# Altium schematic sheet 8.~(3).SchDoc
size 398 x 287 mm
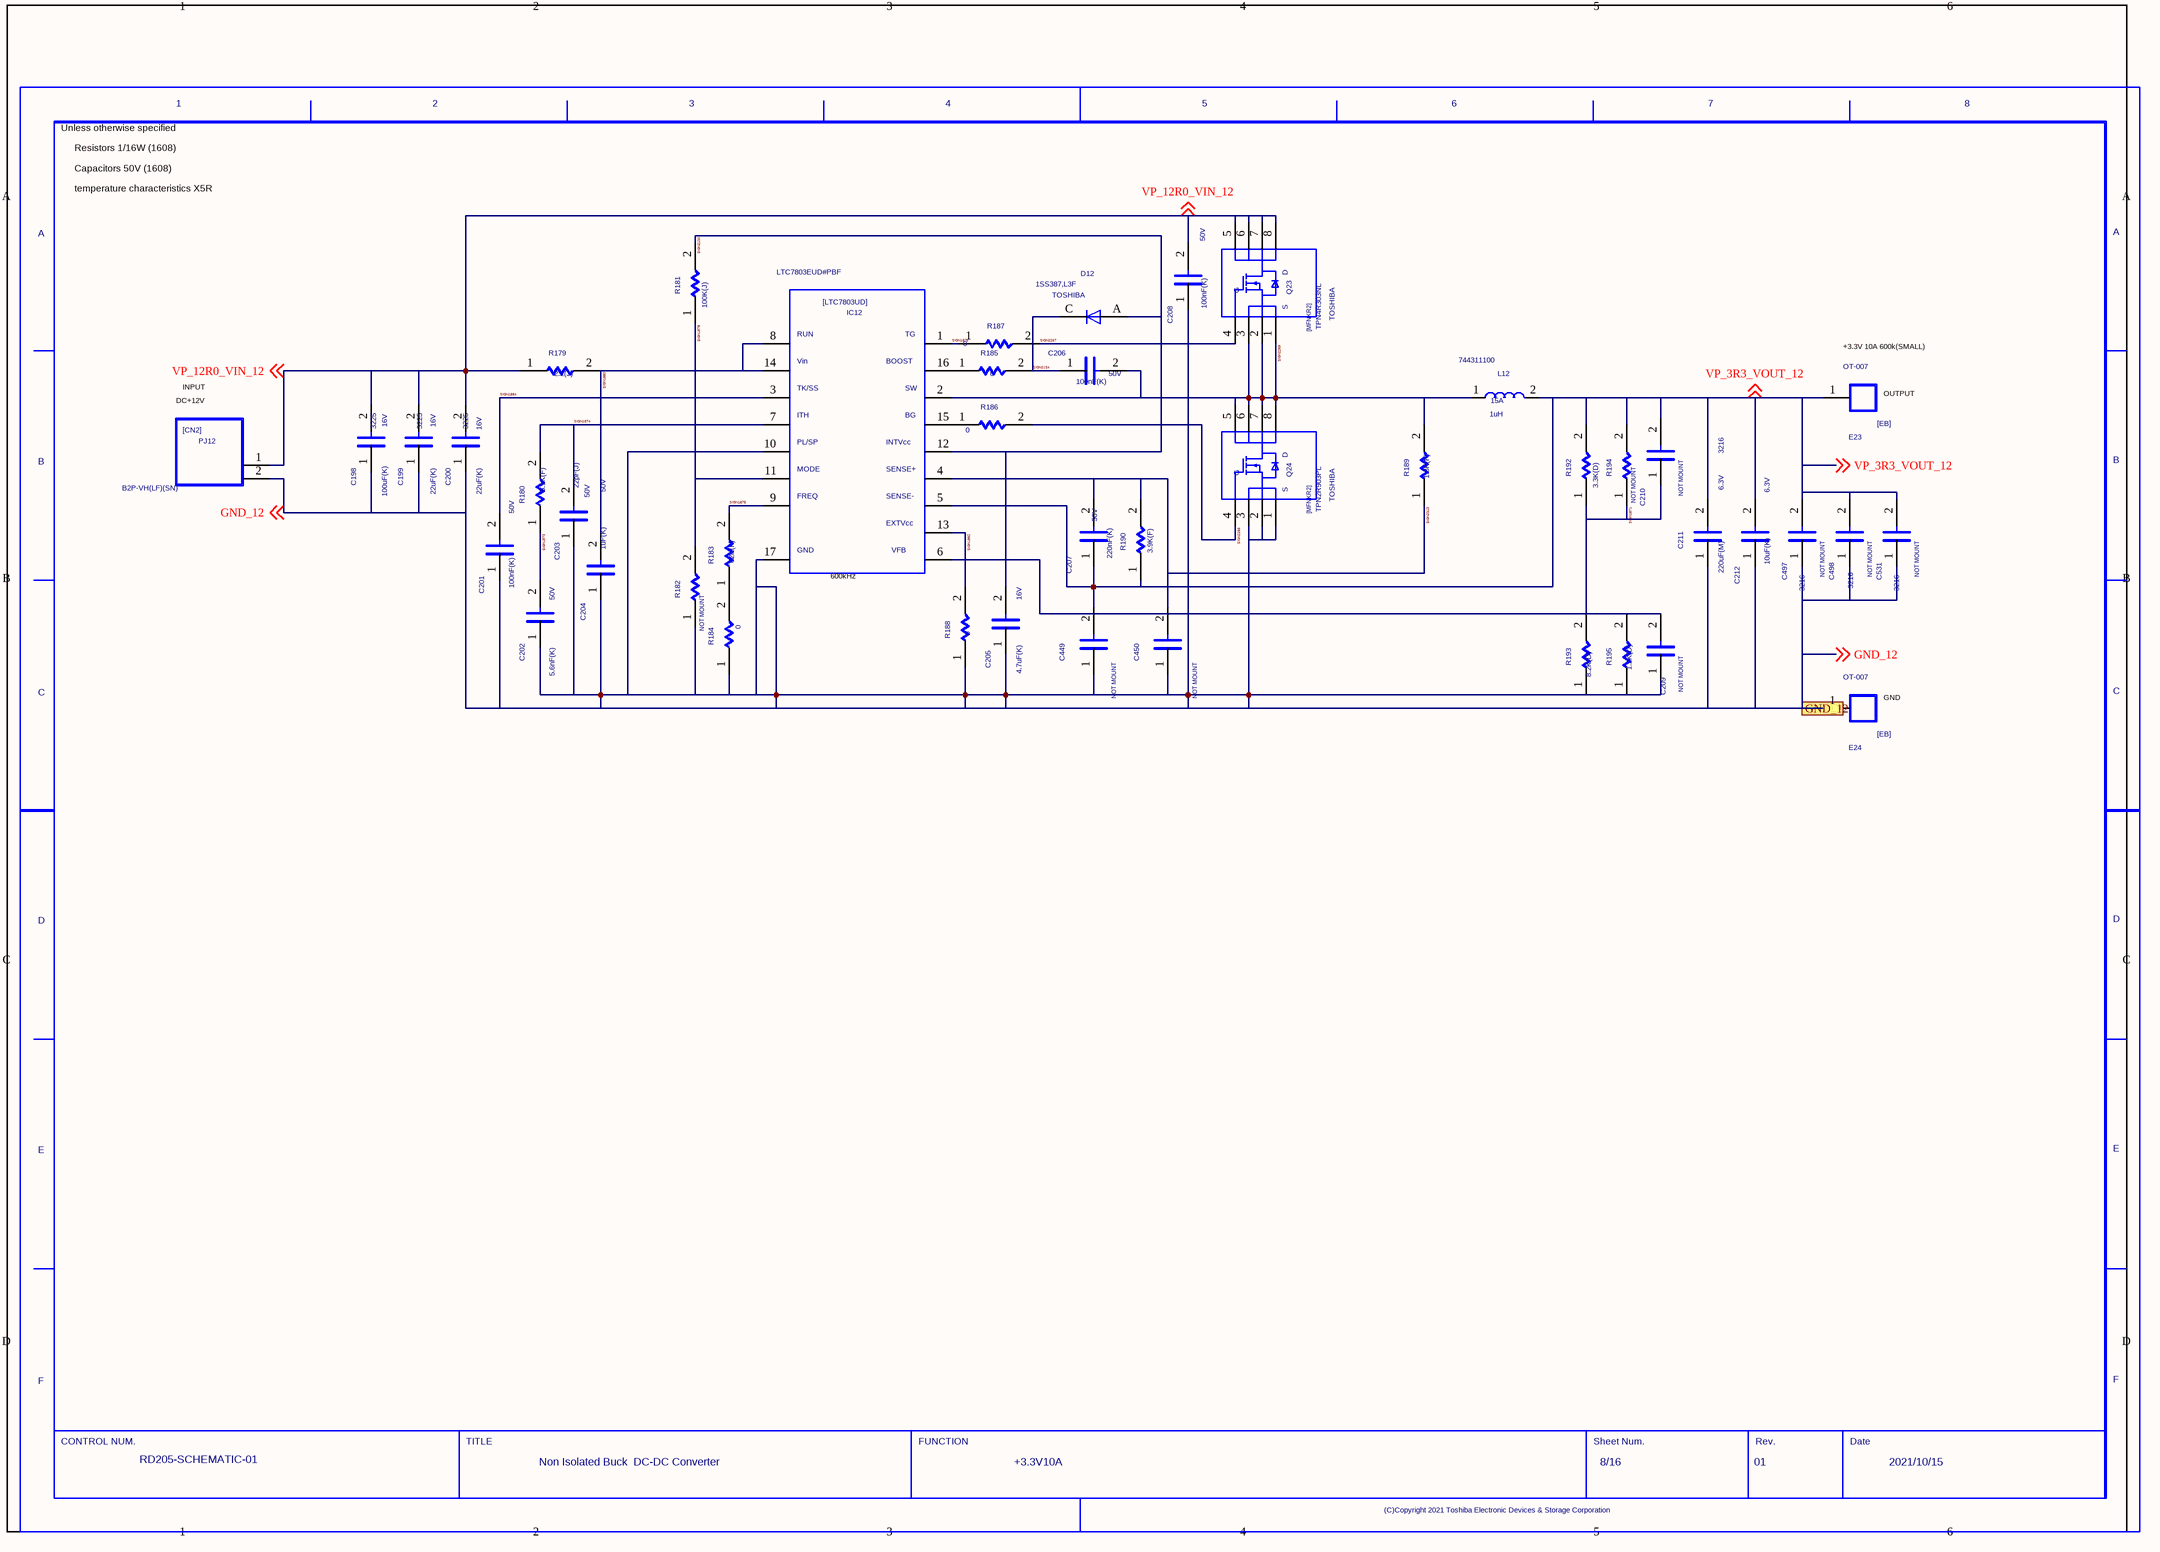
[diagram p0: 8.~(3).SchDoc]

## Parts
C198  SIZECODESMD: 3225  VAL2: 16V  VAL1: 100uF(K)  (hidden comment: C)
C199  SIZECODESMD: 3225  VAL2: 16V  VAL1: 22uF(K)  (hidden comment: C)
C200  SIZECODESMD: 3225  VAL2: 16V  VAL1: 22uF(K)  (hidden comment: C)
C201  VAL2: 50V  VAL1: 100nF(K)  (hidden comment: C)
C202  VAL2: 50V  VAL1: 5.6nF(K)  (hidden comment: C)
C203  VAL2: 50V  VAL1: 22pF(J)  (hidden comment: C)
C204  VAL2: 50V  VAL1: 1uF(K)  (hidden comment: C)
C205  VAL2: 16V  VAL1: 4.7uF(K)  (hidden comment: C)
C206  VAL2: 50V  VAL1: 100nF(K)  (hidden comment: C)
C207  VAL2: 50V  VAL1: 220nF(K)  (hidden comment: C)
C208  VAL2: 50V  VAL1: 100nF(K)  (hidden comment: C)
C209  NOTMOUNT: NOT MOUNT  (hidden comment: C)
C210  NOTMOUNT: NOT MOUNT  (hidden comment: C)
C211  SIZECODESMD: 3216  VAL2: 6.3V  VAL1: 220uF(M)  (hidden comment: C)
C212  VAL2: 6.3V  VAL1: 10uF(K)  (hidden comment: C)
C449  NOTMOUNT: NOT MOUNT  (hidden comment: C)
C450  NOTMOUNT: NOT MOUNT  (hidden comment: C)
C497  NOTMOUNT: NOT MOUNT  SIZECODESMD: 3216  (hidden comment: C)
C498  NOTMOUNT: NOT MOUNT  SIZECODESMD: 3216  (hidden comment: C)
C531  NOTMOUNT: NOT MOUNT  SIZECODESMD: 3216  (hidden comment: C)
D12  USERCOMPTEXT3: TOSHIBA  VAL3: 1SS387,L3F  (hidden comment: D)
E23  VAL3: OT-007  (hidden comment: EB)
E24  VAL3: OT-007  (hidden comment: EB)
IC12  VAL3: LTC7803EUD#PBF  (hidden comment: LTC7803UD)
L12  VAL3: 744311100  VAL2: 15A  VAL1: 1uH  (hidden comment: L)
PJ12  VAL3: B2P-VH(LF)(SN)  (hidden comment: CN2)
Q23  USERCOMPTEXT3: TOSHIBA  VAL3: TPN4R303NL  (hidden comment: MFNKR2)
Q24  USERCOMPTEXT3: TOSHIBA  VAL3: TPN2R903PL  (hidden comment: MFNKR2)
R179  VAL1: 2.2(J)  (hidden comment: R)
R180  VAL1: 5.1K(F)  (hidden comment: R)
R181  VAL1: 100K(J)  (hidden comment: R)
R182  NOTMOUNT: NOT MOUNT  (hidden comment: R)
R183  VAL1: 62K(F)  (hidden comment: R)
R184  VAL1: 0  (hidden comment: R)
R185  VAL1: 0  (hidden comment: R)
R186  VAL1: 0  (hidden comment: R)
R187  VAL1: 0  (hidden comment: R)
R188  VAL1: 0  (hidden comment: R)
R189  VAL1: 1.3K(F)  (hidden comment: R)
R190  VAL1: 3.9K(F)  (hidden comment: R)
R192  VAL1: 3.3K(D)  (hidden comment: R)
R193  VAL1: 8.2K(D)  (hidden comment: R)
R194  NOTMOUNT: NOT MOUNT  (hidden comment: R)
R195  VAL1: 1.2K(D)  (hidden comment: R)
U?  DATE: 2021/10/15  SHEETNUMBER: 8/16  TITLE: Non Isolated Buck / DC-DC Converter  REVISION: 01  DRAWINGNUMBER: RD205-SCHEMATIC-01  FUNCTION: +3.3V10A  (hidden comment: WAKU_DEF100)

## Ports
GND_12

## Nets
GND_12: C198.1 C199.1 C200.1 C201.1 C202.1 C203.1 C204.1 C205.1 C208.1 C209.1 C211.1 C212.1 C449.1 C450.1 C497.1 C498.1 C531.1 E24.1 IC12.10 IC12.17 PJ12.2 Q24.1 Q24.2 Q24.3 R182.1 R184.1 R188.1 R193.1 R195.1 ; off-sheet GND_12, port GND_12
SIGN1871: C209.2 C210.1 IC12.6 R192.1 R193.2 R194.1 R195.2
SIGN1873: C202.2 R180.1
SIGN1874: C203.2 IC12.7 R180.2
SIGN1875: IC12.9 R183.2
SIGN1876: IC12.1 R187.1
SIGN1878: IC12.11 R181.1 R182.2
SIGN1880: C204.2 IC12.8 IC12.14 R179.2
SIGN1882: IC12.13 R188.2
SIGN1884: C201.2 IC12.3
SIGN2133: C205.2 D12.A IC12.12 R181.2
SIGN2134: C206.1 D12.C R185.2
SIGN2267: Q23.4 R187.2
SIGN2268: Q24.4 R186.2
SIGN2269: C206.2 IC12.2 L12.1 Q23.1 Q23.2 Q23.3 Q24.5 Q24.6 Q24.7 Q24.8 R189.2
SIGN2313: C207.2 C450.2 IC12.4 R189.1 R190.2
VP_3R3_VOUT_12: C207.1 C210.2 C211.2 C212.2 C449.2 C497.2 C498.2 C531.2 E23.1 IC12.5 L12.2 R190.1 R192.2 R194.2 ; off-sheet VP_3R3_VOUT_12
VP_12R0_VIN_12: C198.2 C199.2 C200.2 C208.2 PJ12.1 Q23.5 Q23.6 Q23.7 Q23.8 R179.1 ; off-sheet VP_12R0_VIN_12
NetIC12_15: IC12.15 R186.1
NetIC12_16: IC12.16 R185.1
NetR183_1: R183.1 R184.2

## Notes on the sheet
- Unless otherwise specified
- Capacitors 50V (1608)
- Resistors 1/16W (1608)
- temperature characteristics X5R
- DC+12V
- INPUT
- (near E23) +3.3V 10A 600k(SMALL)
- (near E23) OUTPUT
- (near IC12) 600kHz
- (near E24) GND

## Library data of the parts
C198 = C: SQ_PART_MODEL: CON_100n; FNPARTSNAMEG: CHIP CERAMIC CAPACITOR (3225); USEINPARTSLIST: YES; OriginalSymbolOrigin: (2540,7620); MFSOLDERINGPROP: .; TEMPCHARACTERI2: B; MFFORMINGDIVP: KC; OUMECLASSIFICATION: セラミックコンデンサ; MFMOUNTSYMBOLP: 90; CDMASTERCADCELG: DC903A; PCODE: P03276001115; FNCLASSCODEG: P03-03; MAXGCOUNT: 1; RATEDVOLTAGE: 250; COMPONENTNAME: G36030160049; OUMEMAKER: KYC 京セラ; MFPACKAGEMETHOP: S; NOMINALCAPACITA: 100n; OUMEMAKERKATAMEI: CF32W5R104K250AT; CAPACITANCETOLE: K
C199 C200 = C: SQ_PART_MODEL: CON_22u; FNPARTSNAMEG: CHIP CERAMIC CAPACITOR (3225); USEINPARTSLIST: YES; OriginalSymbolOrigin: (2540,7620); MFSOLDERINGPROP: .; TEMPCHARACTERI2: B; MFFORMINGDIVP: KC; OUMECLASSIFICATION: セラミックコンデンサ; MFMOUNTSYMBOLP: 80; CDMASTERCADCELG: DC903A; PCODE: P03043035626; FNCLASSCODEG: P03-03; MAXGCOUNT: 1; RATEDVOLTAGE: 6.3; COMPONENTNAME: G36030119054; OUMEMAKER: TYD 太陽誘電; MFPACKAGEMETHOP: S; NOMINALCAPACITA: 22u; OUMEMAKERKATAMEI: JMK325BJ226KM-T; CAPACITANCETOLE: K
C201 C206 C208 = C: SQ_PART_MODEL: CON_100n; FNPARTSNAMEG: CHIP CERAMIC CAPACITOR (1608); USEINPARTSLIST: YES; OriginalSymbolOrigin: (2540,7620); MFSOLDERINGPROP: .; TEMPCHARACTERI2: B; MFFORMINGDIVP: KC; OUMECLASSIFICATION: セラミックコンデンサ; SIZECODESMD: 1608; MFMOUNTSYMBOLP: 80; CDMASTERCADCELG: C8100E; PCODE: P03B000000E4; FNCLASSCODEG: P03-03; MAXGCOUNT: 1; RATEDVOLTAGE: 16; COMPONENTNAME: GDM030000598; OUMEMAKER: MRT 村田製作所; MFPACKAGEMETHOP: S; NOMINALCAPACITA: 100n; OUMEMAKERKATAMEI: GRM188B11C104KA01C; CAPACITANCETOLE: K
C202 = C: SQ_PART_MODEL: CON_5.6n; FNPARTSNAMEG: CHIP CERAMIC CAPACITOR (1608); USEINPARTSLIST: YES; OriginalSymbolOrigin: (2540,7620); TOLERANCE: K; ASIMVALUE: 5.6N; MFSOLDERINGPROP: .; TEMPCHARACTERI2: B; MFFORMINGDIVP: KC; OUMECLASSIFICATION: セラミックコンデンサ; SIZECODESMD: 1608; MFMOUNTSYMBOLP: 80; CDMASTERCADCELG: C8100E; PCODE: P03039100222; FNCLASSCODEG: P03-03; MAXGCOUNT: 1; RATEDVOLTAGE: 50; COMPONENTNAME: G36030011068; OUMEMAKER: MRT 村田製作所; MFPACKAGEMETHOP: S; OUMEMAKERKATAMEI: GRM39B562K50PT
C203 = C: SQ_PART_MODEL: CON_22p; FNPARTSNAMEG: CHIP CERAMIC CAPACITOR (1608); USEINPARTSLIST: YES; OriginalSymbolOrigin: (2540,7620); TOLERANCE: J; ASIMVALUE: 22P; CDMASTERCADCELG: C8100E; MFSOLDERINGPROP: .; TEMPCHARACTERI2: CH; MFFORMINGDIVP: KC; OUMECLASSIFICATION: セラミックコンデンサ; SIZECODESMD: 1608; MFMOUNTSYMBOLP: 80; PCODE: P03039A02625; FNCLASSCODEG: P03-03; MAXGCOUNT: 1; RATEDVOLTAGE: 50; COMPONENTNAME: G36030011129; OUMEMAKER: TYD 太陽誘電; MFPACKAGEMETHOP: S; OUMEMAKERKATAMEI: UMK107CH220JZ-T
C204 = C: SQ_PART_MODEL: CON_1u; FNPARTSNAMEG: CHIP CERAMIC CAPACITOR (1608); USEINPARTSLIST: YES; OriginalSymbolOrigin: (2540,7620); MFSOLDERINGPROP: .; TEMPCHARACTERI2: B; MFFORMINGDIVP: KC; OUMECLASSIFICATION: セラミックコンデンサ; SIZECODESMD: 1608; MFMOUNTSYMBOLP: 80; CDMASTERCADCELG: C8100E; PCODE: P03039ACE122; FNCLASSCODEG: P03-03; MAXGCOUNT: 1; RATEDVOLTAGE: 6.3; COMPONENTNAME: G36030104159; OUMEMAKER: KYC 京セラ; MFPACKAGEMETHOP: S; NOMINALCAPACITA: 1u; OUMEMAKERKATAMEI: CM105B105K06ATN; CAPACITANCETOLE: K
C205 = C: SQ_PART_MODEL: CON_4.7u; FNPARTSNAMEG: CHIP CERAMIC CAPACITOR (1608); USEINPARTSLIST: YES; OriginalSymbolOrigin: (2540,7620); MFSOLDERINGPROP: .; TEMPCHARACTERI2: B; MFFORMINGDIVP: KC; OUMECLASSIFICATION: セラミックコンデンサ; SIZECODESMD: 1608; MFMOUNTSYMBOLP: 80; CDMASTERCADCELG: C8100E; PCODE: P03B000000MS; FNCLASSCODEG: P03-03; MAXGCOUNT: 1; RATEDVOLTAGE: 4; COMPONENTNAME: GDM030000053; OUMEMAKER: KYC 京セラ; MFPACKAGEMETHOP: S; NOMINALCAPACITA: 4.7u; OUMEMAKERKATAMEI: CM105B475M04AT; CAPACITANCETOLE: M
C207 = C: SQ_PART_MODEL: CON_220n; FNPARTSNAMEG: CHIP CERAMIC CAPACITOR (1608); PARTCOMMENT: 代表セル<KC0008> がフットプリントに登録されていません。; USEINPARTSLIST: YES; OriginalSymbolOrigin: (2540,7620); MFSOLDERINGPROP: .; TEMPCHARACTERI2: B; MFFORMINGDIVP: KC; OUMECLASSIFICATION: セラミックコンデンサ; SIZECODESMD: 1608; MFMOUNTSYMBOLP: 80; CDMASTERCADCELG: KC0008; PCODE: P03B000001L3; FNCLASSCODEG: P03-03; MAXGCOUNT: 1; RATEDVOLTAGE: 16; COMPONENTNAME: GDM030001129; OUMEMAKER: MRT 村田製作所; MFPACKAGEMETHOP: S; NOMINALCAPACITA: 220n; OUMEMAKERKATAMEI: GRM188B11C224KA01D; CAPACITANCETOLE: K
C209 C210 = C: SQ_PART_MODEL: CON_100p; FNPARTSNAMEG: CHIP CERAMIC CAPACITOR (1608); USEINPARTSLIST: YES; OriginalSymbolOrigin: (2540,7620); TOLERANCE: J; ASIMVALUE: 100P; MFSOLDERINGPROP: .; TEMPCHARACTERI2: CH; MFFORMINGDIVP: KC; OUMECLASSIFICATION: セラミックコンデンサ; SIZECODESMD: 1608; MFMOUNTSYMBOLP: 80; CDMASTERCADCELG: C8100E; PCODE: P03039177125; FNCLASSCODEG: P03-03; MAXGCOUNT: 1; RATEDVOLTAGE: 50; COMPONENTNAME: G36030011365; OUMEMAKER: KYC 京セラ; MFPACKAGEMETHOP: S; OUMEMAKERKATAMEI: CM105CH101J50AT; VAL2: 50V; VAL1: 100pF(J)
C211 = C: SQ_PART_MODEL: CON_22u; FNPARTSNAMEG: CHIP CERAMIC CAPACITOR (3216); USEINPARTSLIST: YES; OriginalSymbolOrigin: (2540,7620); MFSOLDERINGPROP: .; TEMPCHARACTERI2: B; MFFORMINGDIVP: KC; OUMECLASSIFICATION: セラミックコンデンサ; MFMOUNTSYMBOLP: 80; CDMASTERCADCELG: DC901A; PCODE: P03B0000004V; FNCLASSCODEG: P03-03; MAXGCOUNT: 1; RATEDVOLTAGE: 6.3; COMPONENTNAME: GDM030000020; OUMEMAKER: KYC 京セラ; MFPACKAGEMETHOP: S; NOMINALCAPACITA: 22u; OUMEMAKERKATAMEI: CM316B226M06AT; CAPACITANCETOLE: M
C212 = C: SQ_PART_MODEL: CON_1u; FNPARTSNAMEG: CHIP CERAMIC CAPACITOR (1608); PARTCOMMENT: 代表セル<KC0008> がフットプリントに登録されていません。; USEINPARTSLIST: YES; OriginalSymbolOrigin: (2540,7620); MFSOLDERINGPROP: .; TEMPCHARACTERI2: B; MFPACKAGEMETHOP: S; MFFORMINGDIVP: KC; MFMOUNTSYMBOLP: 80; PCODE: P03B000000ZQ; OUMECLASSIFICATION: セラミックコンデンサ; SIZECODESMD: 1608; CDMASTERCADCELG: KC0008; FNCLASSCODEG: P03-03; MAXGCOUNT: 1; RATEDVOLTAGE: 6.3; COMPONENTNAME: GDM030000202; OUMEMAKER: MRT 村田製作所; NOMINALCAPACITA: 1u; OUMEMAKERKATAMEI: GRM185B10J105KE21D; CAPACITANCETOLE: K
C449 C450 = C: SQ_PART_MODEL: CON_220n; FNPARTSNAMEG: CHIP CERAMIC CAPACITOR (1608); PARTCOMMENT: 代表セル<KC0008> がフットプリントに登録されていません。; USEINPARTSLIST: YES; OriginalSymbolOrigin: (2540,7620); MFSOLDERINGPROP: .; TEMPCHARACTERI2: B; MFFORMINGDIVP: KC; OUMECLASSIFICATION: セラミックコンデンサ; SIZECODESMD: 1608; MFMOUNTSYMBOLP: 80; CDMASTERCADCELG: KC0008; PCODE: P03B000001L3; FNCLASSCODEG: P03-03; MAXGCOUNT: 1; RATEDVOLTAGE: 16; COMPONENTNAME: GDM030001129; OUMEMAKER: MRT 村田製作所; MFPACKAGEMETHOP: S; NOMINALCAPACITA: 220n; OUMEMAKERKATAMEI: GRM188B11C224KA01D; VAL2: 16V; VAL1: 220nF(K); CAPACITANCETOLE: K
C497 C498 C531 = C: SQ_PART_MODEL: CON_22u; FNPARTSNAMEG: CHIP CERAMIC CAPACITOR (3216); USEINPARTSLIST: YES; OriginalSymbolOrigin: (2540,7620); MFSOLDERINGPROP: .; TEMPCHARACTERI2: B; MFFORMINGDIVP: KC; OUMECLASSIFICATION: セラミックコンデンサ; MFMOUNTSYMBOLP: 80; CDMASTERCADCELG: DC901A; PCODE: P03B0000004V; FNCLASSCODEG: P03-03; MAXGCOUNT: 1; RATEDVOLTAGE: 6.3; COMPONENTNAME: GDM030000020; OUMEMAKER: KYC 京セラ; MFPACKAGEMETHOP: S; NOMINALCAPACITA: 22u; OUMEMAKERKATAMEI: CM316B226M06AT; VAL2: 6.3V; VAL1: 22uF(M); CAPACITANCETOLE: M
D12 = D: FNPARTSNAMEG: DIODE; USEINPARTSLIST: YES; PARTNAME: GDM420000143; SAVEAREA0: -565,-171,12979,8058; SAVECOUNT: 1; TIME: 14:49:55; UPDATEUSER: 19870035; UPDATETIME: 14:20:16; OriginalSymbolOrigin: (5080,5080); FORWARDVOLTAGEM: 0; MAXREVERSEVOLTA: 80; COMPONENTNAME: GDM420000143_package; MFSOLDERINGPROP: .; OUMEMAKER: TSB 東芝（ＹＰＳＳ）; QUADMODEL: dummymodel; MFPACKAGEMETHOP: S; MFFORMINGDIVP: MM; MOUNTINGFORMSMD: SMD; OUMECLASSIFICATION: 小信号ダイオード; OUMEMAKERKATAMEI: 1SS387(TPH3,F); CDMASTERCADCELG: D8101D; PCODE: P42B0000008E; FNCLASSCODEG: P42-01
E23 E24 = EB: FNPARTSNAMEG: TERMINAL; USEINPARTSLIST: YES; PARTNAME: 5P9L1232P001; OUMEPARTTYPE: TB; OriginalSymbolOrigin: (2540,12700); COMPONENTNAME: 5P9L1232P001_package; MAXGCOUNT: 1; MFSOLDERINGPROP: .; OUMEMAKER: オサダ; QUADMODEL: dummymodel; MFPACKAGEMETHOP: I; MFFORMINGDIVP: OD; OUMECLASSIFICATION: 端子台、端子板; CDMASTERCADCELG: DE0009; KIND: PBS; PCODE: P29045001117; TERMINALSTYLE: SC; FNCLASSCODEG: P29-01
IC12 = LTC7803UD: USEINPARTSLIST: YES; SAVECOUNT: 29; SAVEAREA0: -53177,0,89020,58420; TIME: 16:14:14; UPDATEUSER: q91866sr; UPDATETIME: 13:15:36; OriginalSymbolOrigin: (5080,55880); MAXGCOUNT: 1; COMPONENTNAME: LTC7803UD_LTC7803UD; OUMEMAKER: ANALOG DEVICES
L12 = L: USEINPARTSLIST: YES; OriginalSymbolOrigin: (2540,5080); MAXGCOUNT: 1; COMPONENTNAME: L_L; OUMEMAKER: WURTH
PJ12 = CN2: FNPARTSNAMEG: 3.96PITCH NYLON CONNECTOR; USEINPARTSLIST: YES; PARTNAME: G36220114012; OUMEPARTTYPE: CN; OriginalSymbolOrigin: (2540,15240); MAXGCOUNT: 1; RATEDCURRENT: 7; COMPONENTNAME: G36220114012_package; MFSOLDERINGPROP: .; OUMEMAKER: JST 日本圧着端子製造; NUMBEROFCONTACT: 2; QUADMODEL: dummymodel; MFPACKAGEMETHOP: I; MFFORMINGDIVP: CU; CONTACTPITCH: 3.96m; OUMEMAKERKATAMEI: B2P-VH; CDMASTERCADCELG: DPJ514; PCODE: P22346001114; TERMINALSTYLE: PW; FNCLASSCODEG: P22-10
Q23 Q24 = MFNKR2: USEINPARTSLIST: YES; PARTNAME: TPN1R603PL; SAVEAREA0: -9199,-39,32138,22820; TIME: 18:57:44; UPDATEUSER: q91866sr; UPDATETIME: 12:36:02; SAVECOUNT: 10; OriginalSymbolOrigin: (5080,20320); MAXGCOUNT: 1; COMPONENTNAME: MFNKR2_MFNKR2
R179 = R: SQ_PART_MODEL: RES_2.2; FNPARTSNAMEG: CHIP RESISTOR (1608); USEINPARTSLIST: YES; OriginalSymbolOrigin: (5080,5080); TOLERANCE: J; ASIMVALUE: 2.2; MAXGCOUNT: 1; COMPONENTNAME: G36010011507; MFSOLDERINGPROP: .; OUMEMAKER: NAE 松下電子部品; MFPACKAGEMETHOP: S; MFFORMINGDIVP: KC; MOUNTINGFORMSMD: SMD; OUMECLASSIFICATION: 表面実装用固定抵抗器; MFMOUNTSYMBOLP: 80; POWERRATING: 63m; OUMEMAKERKATAMEI: ERJ3GEYJ2R2V; NUMBEROFELEMENT: 0; VAL2: 62.5mW; CDMASTERCADCELG: DR802R; PCODE: P01042157622; FNCLASSCODEG: P01-08
R180 = R: SQ_PART_MODEL: RES_5.1K; FNPARTSNAMEG: CHIP RESISTOR (1608); USEINPARTSLIST: YES; OriginalSymbolOrigin: (5080,5080); MAXGCOUNT: 1; COMPONENTNAME: G5101105N106; MFSOLDERINGPROP: .; OUMEMAKER: NAE 松下電子部品; MFPACKAGEMETHOP: S; MFFORMINGDIVP: KC; MOUNTINGFORMSMD: SMD; OUMECLASSIFICATION: 表面実装用固定抵抗器; RESISTANCETOLER: F; MFMOUNTSYMBOLP: 80; POWERRATING: 63m; OUMEMAKERKATAMEI: ERJ3GEYF512V; NOMINALRESISTAN: 5.1K; NUMBEROFELEMENT: 0; VAL2: 62.5mW; CDMASTERCADCELG: DR802R; PCODE: P01042378621; FNCLASSCODEG: P01-08
R181 = R: SQ_PART_MODEL: RES_100K; FNPARTSNAMEG: CHIP RESISTOR (1608); USEINPARTSLIST: YES; OriginalSymbolOrigin: (5080,5080); TOLERANCE: J; ASIMVALUE: 100K; MFSOLDERINGPROP: .; MFPACKAGEMETHOP: S; MFFORMINGDIVP: KC; MOUNTINGFORMSMD: SMD; MFMOUNTSYMBOLP: 80; NUMBEROFELEMENT: 0; PCODE: P01042047220; MAXGCOUNT: 1; COMPONENTNAME: G36010011057; OUMEMAKER: HDK 北陸電気工業; OUMECLASSIFICATION: 表面実装用固定抵抗器; POWERRATING: 63m; OUMEMAKERKATAMEI: CR1/16 104JV; VAL2: 62.5mW; CDMASTERCADCELG: DR802R; FNCLASSCODEG: P01-08
R182 = R: SQ_PART_MODEL: RES_10; FNPARTSNAMEG: CHIP RESISTOR (1608); USEINPARTSLIST: YES; OriginalSymbolOrigin: (5080,5080); TOLERANCE: F; ASIMVALUE: 10; MFSOLDERINGPROP: .; MFPACKAGEMETHOP: S; MFFORMINGDIVP: KC; MOUNTINGFORMSMD: SMD; MFMOUNTSYMBOLP: 80; NUMBEROFELEMENT: 0; PCODE: P01042036620; MAXGCOUNT: 1; COMPONENTNAME: G36010104063; OUMEMAKER: NAE 松下電子部品; OUMECLASSIFICATION: 表面実装用固定抵抗器; POWERRATING: 63m; OUMEMAKERKATAMEI: ERJ3GEYF100V; VAL2: 62.5mW; VAL1: 10(F); CDMASTERCADCELG: DR802R; FNCLASSCODEG: P01-08
R183 = R: SQ_PART_MODEL: RES_62K; FNPARTSNAMEG: CHIP RESISTOR (1608); USEINPARTSLIST: YES; OriginalSymbolOrigin: (5080,5080); MAXGCOUNT: 1; COMPONENTNAME: GDM010001037; MFSOLDERINGPROP: .; OUMEMAKER: NAE 松下電子部品; MFPACKAGEMETHOP: S; MFFORMINGDIVP: KC; MOUNTINGFORMSMD: SMD; OUMECLASSIFICATION: 表面実装用固定抵抗器; RESISTANCETOLER: F; MFMOUNTSYMBOLP: 80; POWERRATING: 63m; OUMEMAKERKATAMEI: ERJ3GEYF623V; NOMINALRESISTAN: 62K; NUMBEROFELEMENT: 0; VAL2: 62.5mW; CDMASTERCADCELG: DR802R; PCODE: P01042441622; FNCLASSCODEG: P01-08
R184 = R: SQ_PART_MODEL: RES_160K; FNPARTSNAMEG: CHIP RESISTOR (1608); USEINPARTSLIST: YES; OriginalSymbolOrigin: (5080,5080); MAXGCOUNT: 1; COMPONENTNAME: G51011061108; MFSOLDERINGPROP: .; OUMEMAKER: HDK 北陸電気工業; MFPACKAGEMETHOP: S; MFFORMINGDIVP: KC; MOUNTINGFORMSMD: SMD; OUMECLASSIFICATION: 表面実装用固定抵抗器; RESISTANCETOLER: F; MFMOUNTSYMBOLP: 80; POWERRATING: 63m; OUMEMAKERKATAMEI: CR1/16 164FV; NOMINALRESISTAN: 160K; VAL2: 62.5mW; CDMASTERCADCELG: DR802R; PCODE: P01042125225; FNCLASSCODEG: P01-08
R185 R188 = R: SQ_PART_MODEL: RES_10; FNPARTSNAMEG: CHIP RESISTOR (1608); USEINPARTSLIST: YES; OriginalSymbolOrigin: (5080,5080); TOLERANCE: F; ASIMVALUE: 10; MFSOLDERINGPROP: .; MFPACKAGEMETHOP: S; MFFORMINGDIVP: KC; MOUNTINGFORMSMD: SMD; MFMOUNTSYMBOLP: 80; PCODE: P01042036620; MAXGCOUNT: 1; COMPONENTNAME: G36010104063; OUMEMAKER: NAE 松下電子部品; OUMECLASSIFICATION: 表面実装用固定抵抗器; POWERRATING: 63m; OUMEMAKERKATAMEI: ERJ3GEYF100V; VAL2: 62.5mW; CDMASTERCADCELG: DR802R; FNCLASSCODEG: P01-08
R186 R187 = R: SQ_PART_MODEL: RES_10; FNPARTSNAMEG: CHIP RESISTOR (2012); USEINPARTSLIST: YES; OriginalSymbolOrigin: (5080,5080); MAXGCOUNT: 1; TOLERANCE: F; COMPONENTNAME: 5P9L1083P100; MFSOLDERINGPROP: .; OUMEMAKER: 北陸電気工業; MFPACKAGEMETHOP: S; MFFORMINGDIVP: KC; MOUNTINGFORMSMD: SMD; OUMECLASSIFICATION: 表面実装用固定抵抗器; ASIMVALUE: 10; MFMOUNTSYMBOLP: 90; POWERRATING: 100m; OUMEMAKERKATAMEI: CR1/10 100FV Pb(F); VAL2: 125mW; CDMASTERCADCELG: DR910A; PCODE: P01043091222; FNCLASSCODEG: P01-08
R189 = R: SQ_PART_MODEL: RES_1.3K; FNPARTSNAMEG: CHIP RESISTOR (1608); USEINPARTSLIST: YES; OriginalSymbolOrigin: (5080,5080); TOLERANCE: F; ASIMVALUE: 1.3K; MAXGCOUNT: 1; COMPONENTNAME: G36010104049; MFSOLDERINGPROP: .; OUMEMAKER: HDK 北陸電気工業; MFPACKAGEMETHOP: S; MFFORMINGDIVP: KC; MOUNTINGFORMSMD: SMD; OUMECLASSIFICATION: 表面実装用固定抵抗器; MFMOUNTSYMBOLP: 80; POWERRATING: 63m; OUMEMAKERKATAMEI: CR1/16 132FV; NUMBEROFELEMENT: 0; VAL2: 62.5mW; CDMASTERCADCELG: DR802R; PCODE: P01042017223; FNCLASSCODEG: P01-08
R190 = R: SQ_PART_MODEL: RES_3.9K; FNPARTSNAMEG: CHIP RESISTOR (1608); USEINPARTSLIST: YES; OriginalSymbolOrigin: (5080,5080); MAXGCOUNT: 1; COMPONENTNAME: G36010104254; OUMEMAKER: HDK 北陸電気工業; MOUNTINGFORMSMD: SMD; OUMECLASSIFICATION: 表面実装用固定抵抗器; RESISTANCETOLER: F; POWERRATING: 63m; OUMEMAKERKATAMEI: CR1/16 392FV; NOMINALRESISTAN: 3.9K; CDMASTERCADCELG: DR802R; MFSOLDERINGPROP: .; MFPACKAGEMETHOP: S; MFFORMINGDIVP: KC; MFMOUNTSYMBOLP: 80; NUMBEROFELEMENT: 0; VAL2: 62.5mW; PCODE: P01042262227; FNCLASSCODEG: P01-08
R192 = R: SQ_PART_MODEL: RES_3.3K; FNPARTSNAMEG: CHIP RESISTOR (1608); USEINPARTSLIST: YES; OriginalSymbolOrigin: (5080,5080); MAXGCOUNT: 1; COMPONENTNAME: G36010014485; MFSOLDERINGPROP: .; OUMEMAKER: SSM 進工業; MFPACKAGEMETHOP: S; MFFORMINGDIVP: KC; MOUNTINGFORMSMD: SMD; OUMECLASSIFICATION: 表面実装用固定抵抗器; RESISTANCETOLER: D; MFMOUNTSYMBOLP: 80; POWERRATING: 63m; OUMEMAKERKATAMEI: RR0816P-332-D; NOMINALRESISTAN: 3.3K; NUMBEROFELEMENT: 0; VAL2: 62.5mW; CDMASTERCADCELG: DR802R; PCODE: P01042249822; FNCLASSCODEG: P01-08
R193 = R: ICX_PART_MODEL: RES_8.2K; FNPARTSNAMEG: CHIP RESISTOR (1608); OriginalSymbolOrigin: (5080,5080); FNCLASSCODEG: P01-08; PCODE: P01117051114; CDMASTERCADCELG: DR802R; USEWITHSCHEMA: YES; VAL2: 62.5mW; NUMBEROFELEMENT: 0; NOMINALRESISTAN: 8.2K; OUMEMAKERKATAMEI: RK73G1JTD822D; POWERRATING: 63m; MFMOUNTSYMBOLP: 80; RESISTANCETOLER: D; FUNCTION: G36010129479; OUMECLASSIFICATION: 表面実装用固定抵抗器; MOUNTINGFORMSMD: SMD; MFFORMINGDIVP: KC; MFPACKAGEMETHOP: S; OUMEMAKER: KOA ＫＯＡ; MFSOLDERINGPROP: .; MAXGCOUNT: 1
R194 = R: SQ_PART_MODEL: RES_3.3K; FNPARTSNAMEG: CHIP RESISTOR (1608); USEINPARTSLIST: YES; OriginalSymbolOrigin: (5080,5080); TOLERANCE: F; ASIMVALUE: 3.3K; MAXGCOUNT: 1; COMPONENTNAME: G36010027027; MFSOLDERINGPROP: .; OUMEMAKER: ROH ロー・; MFPACKAGEMETHOP: S; MFFORMINGDIVP: KC; MOUNTINGFORMSMD: SMD; OUMECLASSIFICATION: 表面実装用固定抵抗器; MFMOUNTSYMBOLP: 80; POWERRATING: 63m; OUMEMAKERKATAMEI: MCR03EZPFX3301; NUMBEROFELEMENT: 0; VAL2: 62.5mW; VAL1: 3.3K(F); CDMASTERCADCELG: DR802R; PCODE: P01042250729; FNCLASSCODEG: P01-08
R195 = R: ICX_PART_MODEL: RES_1.2K; FNPARTSNAMEG: CHIP RESISTOR (1608); OriginalSymbolOrigin: (5080,5080); FNCLASSCODEG: P01-08; PCODE: P01117031116; CDMASTERCADCELG: DR802R; USEWITHSCHEMA: YES; VAL2: 62.5mW; NUMBEROFELEMENT: 0; NOMINALRESISTAN: 1.2K; OUMEMAKERKATAMEI: RK73G1JTD122D; POWERRATING: 63m; MFMOUNTSYMBOLP: 80; RESISTANCETOLER: D; FUNCTION: G36010129271; OUMECLASSIFICATION: 表面実装用固定抵抗器; MOUNTINGFORMSMD: SMD; MFFORMINGDIVP: KC; MFPACKAGEMETHOP: S; OUMEMAKER: KOA ＫＯＡ; MFSOLDERINGPROP: .; MAXGCOUNT: 1
U? = WAKU_DEF100: PLOTTIME: HH:MM; SAVEAREA0: 330961,54,387907,31546; TIME: 19:23:07; UPDATEUSER: t5459927; UPDATETIME: 15:33:40; SAVECOUNT: 6; OriginalSymbolOrigin: (10160,284480); DESIGNED: ***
